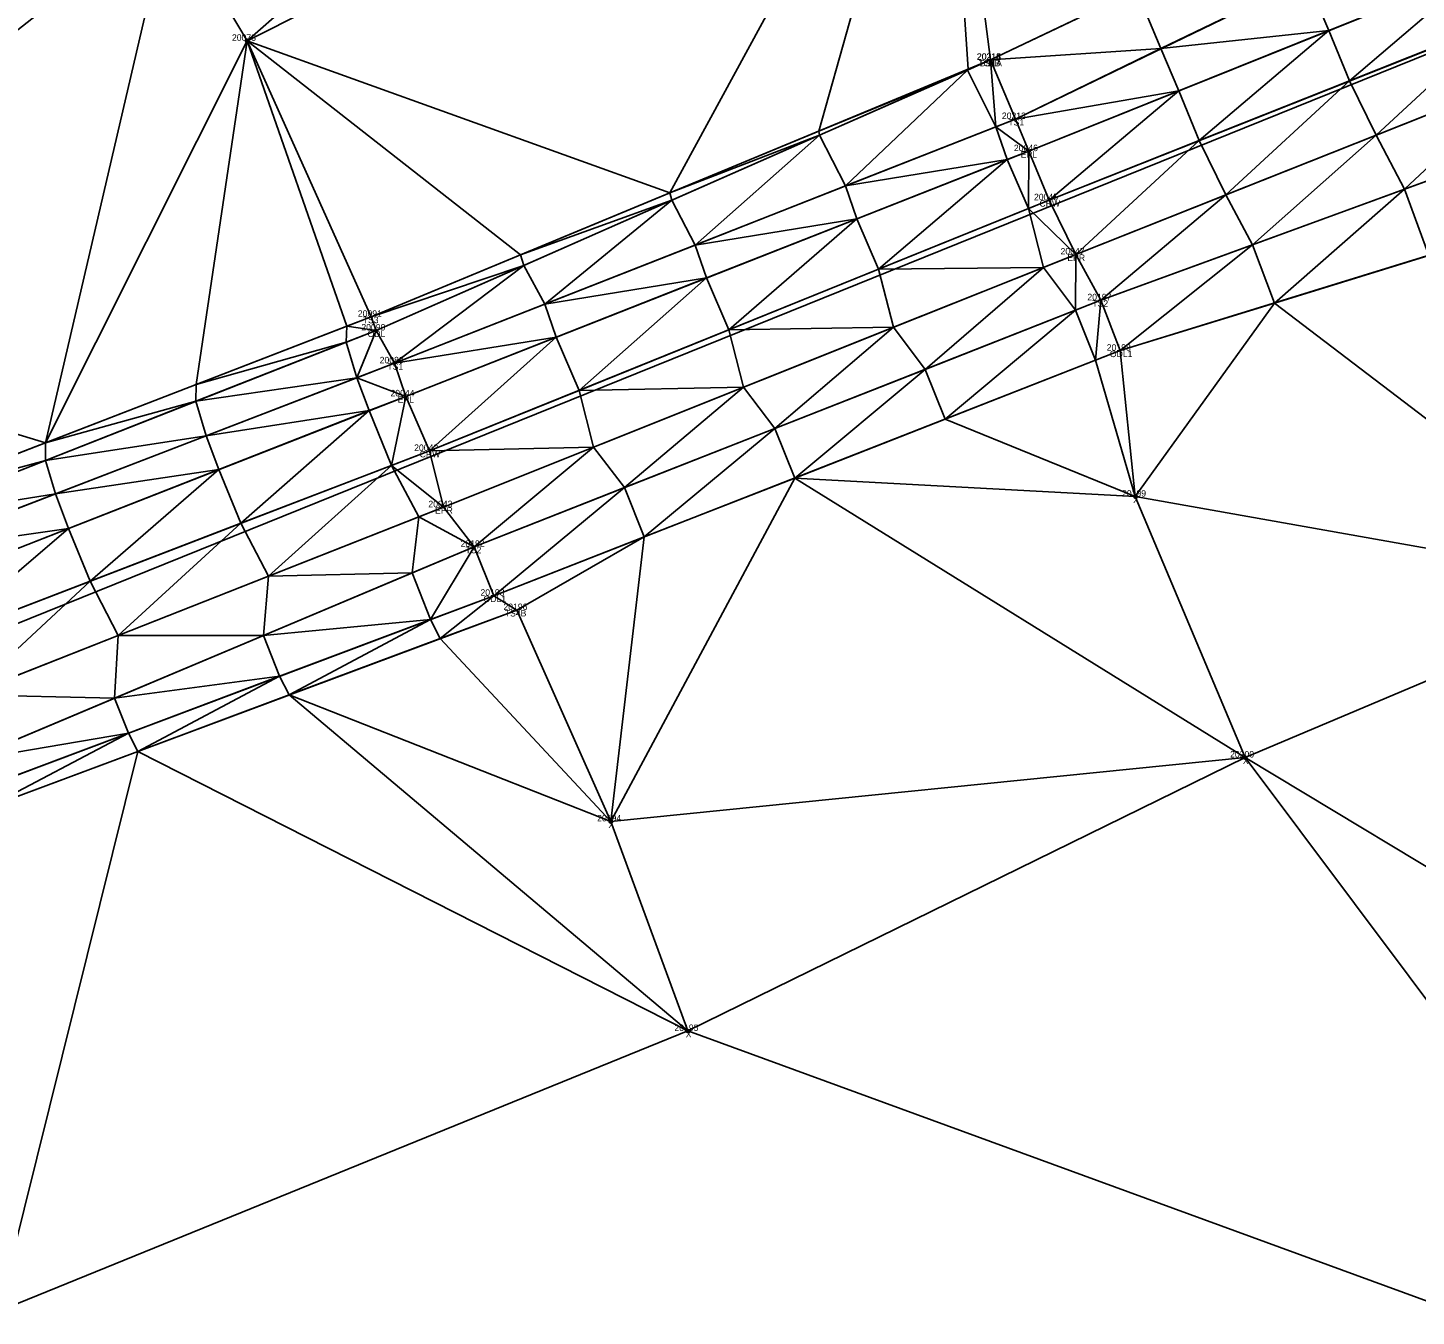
# Model space of a CAD drawing. Extents: x 1966740 to 1969291, y 1117379 to 1118460.
# Drawn here: x 1967411.8 to 1967626.6, y 1117599.2 to 1117798.6 of the extents above; entities that cross this region are included whole.
import ezdxf

# ---------------------------------------------------------------- set-up
doc = ezdxf.new("R2010")
doc.units = 0
for name, color, linetype in [('Level 1', 7, 'Continuous'), ('Level 3', 7, 'Continuous'), ('Level 30', 7, 'Continuous'), ('Level 35', 7, 'Continuous'), ('Level 50', 7, 'Continuous'), ('Level 52', 7, 'Continuous'), ('Level 53', 7, 'Continuous'), ('Level 56', 7, 'Continuous'), ('Level 6', 7, 'Continuous'), ('Level 62', 7, 'Continuous')]:
    doc.layers.add(name, color=color, linetype=linetype)

msp = doc.modelspace()

# ---------------------------------------------------------------- linework, layer by layer
at = {"layer": 'Level 1'}
msp.add_line((1966770.74, 1117448.12), (1967849.47, 1117883.86), dxfattribs=at)
at = {"layer": 'Level 3'}
for points in [[(1967560.73, 1117793.63), (1967650.63, 1117836.46), (1967680.95, 1117850.94), (1967690.95, 1117852.56), (1967700.5, 1117839.06)], [(1966768.15, 1117461.43), (1966869.41, 1117499.34), (1967070.52, 1117582.35), (1967171.25, 1117624.02), (1967269.74, 1117664.9), (1967320.21, 1117685.71), (1967369.37, 1117708.48), (1967468.51, 1117746.66), (1967564.6, 1117784.47), (1967654.68, 1117828.05), (1967680.1, 1117841.48), (1967687.91, 1117842.93), (1967691.45, 1117838.71), (1967693.03, 1117834.22)], [(1966769.51, 1117457.48), (1966870.16, 1117497.34), (1966971.19, 1117538.95), (1967071.09, 1117580.24), (1967172.6, 1117621.53), (1967270.79, 1117661.66), (1967321.12, 1117682.57), (1967371.52, 1117702.88), (1967470.26, 1117741.55), (1967566.67, 1117779.5), (1967661.25, 1117817.53), (1967694.4, 1117831.19), (1967697.89, 1117822.8)], [(1966772.57, 1117449.88), (1966874.49, 1117489.87), (1966974.64, 1117529.93), (1967075.06, 1117571.68), (1967175.91, 1117613.34), (1967274.11, 1117653.69), (1967325.25, 1117674.8), (1967374.73, 1117695.01), (1967473.9, 1117733.1), (1967569.8, 1117771.9), (1967665.19, 1117809.79), (1967697.89, 1117822.8)], [(1967340.03, 1117669.86), (1967379.26, 1117686.2), (1967476.09, 1117724.39), (1967573.92, 1117763.51), (1967667.7, 1117800.74), (1967701.64, 1117814), (1967697.89, 1117822.8)], [(1967334.06, 1117655.75), (1967334.81, 1117659.44), (1967379.1, 1117675.46), (1967480.83, 1117718.27), (1967577.81, 1117756.42), (1967702.07, 1117801.85), (1967703.17, 1117805.75), (1967702.89, 1117809.87)], [(1966766.42, 1117472.19), (1966865.47, 1117508.82), (1967066.64, 1117593.45), (1967166.55, 1117636.11), (1967264.62, 1117677.56), (1967315.66, 1117698.57), (1967367.9, 1117716.34), (1967464.92, 1117753.87), (1967560.73, 1117793.63)], [(1967334.06, 1117655.75), (1967336.84, 1117652.84), (1967381.99, 1117669.13), (1967487.42, 1117708.48)]]:
    msp.add_lwpolyline(points, dxfattribs=at)
at = {"layer": 'Level 30'}
for centre in [(1967445.69, 1117796.58), (1967583.14, 1117726.03), (1967600.11, 1117685.65), (1967501.97, 1117675.76), (1967513.9, 1117643.33)]:
    msp.add_circle(centre, 0.25, dxfattribs=at)
at = {"layer": 'Level 35'}
for points in [[(1967433.7, 1117816.8), (1967539.35, 1117878.65), (1967445.69, 1117796.58)], [(1967445.69, 1117796.58), (1967539.35, 1117878.65), (1967553.36, 1117850.76)], [(1967445.69, 1117796.58), (1967553.36, 1117850.76), (1967511.09, 1117773.03)], [(1967511.09, 1117773.03), (1967553.36, 1117850.76), (1967534.17, 1117782.61)], [(1967534.17, 1117782.61), (1967553.36, 1117850.76), (1967557.25, 1117792.19)], [(1967553.36, 1117850.76), (1967583.3, 1117804.39), (1967560.73, 1117793.63)], [(1967553.36, 1117850.76), (1967560.73, 1117793.63), (1967557.25, 1117792.19)], [(1967352.83, 1117753.13), (1967433.7, 1117816.8), (1967414.52, 1117734.37)], [(1967414.52, 1117734.37), (1967433.7, 1117816.8), (1967445.69, 1117796.58)], [(1967609.61, 1117806.25), (1967636.26, 1117807.48), (1967613.06, 1117798.15)], [(1967613.06, 1117798.15), (1967636.26, 1117807.48), (1967616.27, 1117790.36)], [(1967616.27, 1117790.36), (1967636.26, 1117807.48), (1967639.5, 1117799.59)], [(1967583.3, 1117804.39), (1967609.61, 1117806.25), (1967587.1, 1117795.36)], [(1967587.1, 1117795.36), (1967609.61, 1117806.25), (1967613.06, 1117798.15)], [(1967560.73, 1117793.63), (1967583.3, 1117804.39), (1967587.1, 1117795.36)], [(1967587.1, 1117795.36), (1967613.06, 1117798.15), (1967589.86, 1117788.83)], [(1967589.86, 1117788.83), (1967613.06, 1117798.15), (1967593.04, 1117781.13)], [(1967593.04, 1117781.13), (1967613.06, 1117798.15), (1967616.27, 1117790.36)], [(1967616.27, 1117790.36), (1967639.5, 1117799.59), (1967620.39, 1117781.96)], [(1967620.39, 1117781.96), (1967639.5, 1117799.59), (1967643.63, 1117791.18)], [(1967414.52, 1117734.37), (1967445.69, 1117796.58), (1967437.82, 1117743.38)], [(1967437.82, 1117743.38), (1967445.69, 1117796.58), (1967461.13, 1117752.4)], [(1967445.69, 1117796.58), (1967511.09, 1117773.03), (1967488, 1117763.45)], [(1967445.69, 1117796.58), (1967488, 1117763.45), (1967464.92, 1117753.87)], [(1967445.69, 1117796.58), (1967464.92, 1117753.87), (1967461.13, 1117752.4)], [(1967560.73, 1117793.63), (1967587.1, 1117795.36), (1967564.6, 1117784.47)], [(1967564.6, 1117784.47), (1967587.1, 1117795.36), (1967589.86, 1117788.83)], [(1967534.17, 1117782.61), (1967557.25, 1117792.19), (1967557.15, 1117792.05)], [(1967534.17, 1117782.61), (1967557.15, 1117792.05), (1967534.28, 1117781.98)], [(1967534.28, 1117781.98), (1967557.15, 1117792.05), (1967538.29, 1117774.12)], [(1967538.29, 1117774.12), (1967557.15, 1117792.05), (1967561.56, 1117783.28)], [(1967557.15, 1117792.05), (1967557.25, 1117792.19), (1967560.73, 1117793.63)], [(1967557.15, 1117792.05), (1967560.73, 1117793.63), (1967561.56, 1117783.28)], [(1967560.73, 1117793.63), (1967564.6, 1117784.47), (1967561.56, 1117783.28)], [(1967593.04, 1117781.13), (1967616.27, 1117790.36), (1967597.15, 1117772.73)], [(1967597.15, 1117772.73), (1967616.27, 1117790.36), (1967620.39, 1117781.96)], [(1967620.39, 1117781.96), (1967643.63, 1117791.18), (1967624.77, 1117773.59)], [(1967624.77, 1117773.59), (1967643.63, 1117791.18), (1967648.25, 1117782.17)], [(1967564.6, 1117784.47), (1967589.86, 1117788.83), (1967566.67, 1117779.5)], [(1967566.67, 1117779.5), (1967589.86, 1117788.83), (1967569.8, 1117771.9)], [(1967569.8, 1117771.9), (1967589.86, 1117788.83), (1967593.04, 1117781.13)], [(1967538.29, 1117774.12), (1967561.56, 1117783.28), (1967563.31, 1117778.18)], [(1967561.56, 1117783.28), (1967564.6, 1117784.47), (1967566.67, 1117779.5)], [(1967561.56, 1117783.28), (1967566.67, 1117779.5), (1967563.31, 1117778.18)], [(1967511.09, 1117773.03), (1967534.17, 1117782.61), (1967534.28, 1117781.98)], [(1967511.09, 1117773.03), (1967534.28, 1117781.98), (1967511.41, 1117771.9)], [(1967511.41, 1117771.9), (1967534.28, 1117781.98), (1967515.03, 1117764.97)], [(1967515.03, 1117764.97), (1967534.28, 1117781.98), (1967538.29, 1117774.12)], [(1967569.8, 1117771.9), (1967593.04, 1117781.13), (1967573.92, 1117763.51)], [(1967573.92, 1117763.51), (1967593.04, 1117781.13), (1967597.15, 1117772.73)], [(1967597.15, 1117772.73), (1967620.39, 1117781.96), (1967601.29, 1117765)], [(1967601.29, 1117765), (1967620.39, 1117781.96), (1967624.77, 1117773.59)], [(1967624.77, 1117773.59), (1967648.25, 1117782.17), (1967628.56, 1117763.37)], [(1967563.31, 1117778.18), (1967566.67, 1117779.5), (1967566.59, 1117770.6)], [(1967566.59, 1117770.6), (1967566.67, 1117779.5), (1967569.8, 1117771.9)], [(1967538.29, 1117774.12), (1967563.31, 1117778.18), (1967540.04, 1117769.02)], [(1967540.04, 1117769.02), (1967563.31, 1117778.18), (1967543.42, 1117761.22)], [(1967543.42, 1117761.22), (1967563.31, 1117778.18), (1967566.59, 1117770.6)], [(1967488, 1117763.45), (1967511.09, 1117773.03), (1967511.41, 1117771.9)], [(1967515.03, 1117764.97), (1967538.29, 1117774.12), (1967540.04, 1117769.02)], [(1967573.92, 1117763.51), (1967597.15, 1117772.73), (1967577.81, 1117756.42)], [(1967577.81, 1117756.42), (1967597.15, 1117772.73), (1967601.29, 1117765)], [(1967601.29, 1117765), (1967624.77, 1117773.59), (1967604.68, 1117755.99)], [(1967604.68, 1117755.99), (1967624.77, 1117773.59), (1967628.56, 1117763.37)], [(1967488, 1117763.45), (1967511.41, 1117771.9), (1967488.54, 1117761.82)], [(1967488.54, 1117761.82), (1967511.41, 1117771.9), (1967491.77, 1117755.81)], [(1967491.77, 1117755.81), (1967511.41, 1117771.9), (1967515.03, 1117764.97)], [(1967543.42, 1117761.22), (1967566.59, 1117770.6), (1967568.94, 1117761.51)], [(1967566.59, 1117770.6), (1967569.8, 1117771.9), (1967573.92, 1117763.51)], [(1967566.59, 1117770.6), (1967573.92, 1117763.51), (1967568.94, 1117761.51)], [(1967515.03, 1117764.97), (1967540.04, 1117769.02), (1967516.78, 1117759.87)], [(1967516.78, 1117759.87), (1967540.04, 1117769.02), (1967520.24, 1117751.85)], [(1967520.24, 1117751.85), (1967540.04, 1117769.02), (1967543.42, 1117761.22)], [(1967491.77, 1117755.81), (1967515.03, 1117764.97), (1967516.78, 1117759.87)], [(1967577.81, 1117756.42), (1967601.29, 1117765), (1967580.8, 1117748.62)], [(1967580.8, 1117748.62), (1967601.29, 1117765), (1967604.68, 1117755.99)], [(1967464.92, 1117753.87), (1967488, 1117763.45), (1967488.54, 1117761.82)], [(1967464.92, 1117753.87), (1967488.54, 1117761.82), (1967465.67, 1117751.74)], [(1967465.67, 1117751.74), (1967488.54, 1117761.82), (1967468.51, 1117746.66)], [(1967468.51, 1117746.66), (1967488.54, 1117761.82), (1967491.77, 1117755.81)], [(1967543.42, 1117761.22), (1967568.94, 1117761.51), (1967545.73, 1117752.23)], [(1967545.73, 1117752.23), (1967568.94, 1117761.51), (1967550.62, 1117745.72)], [(1967550.62, 1117745.72), (1967568.94, 1117761.51), (1967573.88, 1117754.87)], [(1967568.94, 1117761.51), (1967573.92, 1117763.51), (1967573.88, 1117754.87)], [(1967573.88, 1117754.87), (1967573.92, 1117763.51), (1967577.81, 1117756.42)], [(1967604.68, 1117755.99), (1967628.56, 1117763.37), (1967662.45, 1117711.98)], [(1967491.77, 1117755.81), (1967516.78, 1117759.87), (1967493.52, 1117750.71)], [(1967493.52, 1117750.71), (1967516.78, 1117759.87), (1967497.07, 1117742.47)], [(1967497.07, 1117742.47), (1967516.78, 1117759.87), (1967520.24, 1117751.85)], [(1967520.24, 1117751.85), (1967543.42, 1117761.22), (1967545.73, 1117752.23)], [(1967468.51, 1117746.66), (1967491.77, 1117755.81), (1967493.52, 1117750.71)], [(1967573.88, 1117754.87), (1967577.81, 1117756.42), (1967576.99, 1117747.13)], [(1967576.99, 1117747.13), (1967577.81, 1117756.42), (1967580.8, 1117748.62)], [(1967580.8, 1117748.62), (1967604.68, 1117755.99), (1967583.14, 1117726.03)], [(1967583.14, 1117726.03), (1967604.68, 1117755.99), (1967662.45, 1117711.98)], [(1967352.83, 1117753.13), (1967414.52, 1117734.37), (1967391.21, 1117725.35)], [(1967461.13, 1117752.4), (1967464.92, 1117753.87), (1967465.67, 1117751.74)], [(1967550.62, 1117745.72), (1967573.88, 1117754.87), (1967553.72, 1117738.02)], [(1967553.72, 1117738.02), (1967573.88, 1117754.87), (1967576.99, 1117747.13)], [(1967437.82, 1117743.38), (1967461.13, 1117752.4), (1967461.04, 1117749.92)], [(1967461.04, 1117749.92), (1967461.13, 1117752.4), (1967465.67, 1117751.74)], [(1967461.04, 1117749.92), (1967465.67, 1117751.74), (1967462.68, 1117744.41)], [(1967462.68, 1117744.41), (1967465.67, 1117751.74), (1967468.51, 1117746.66)], [(1967497.07, 1117742.47), (1967520.24, 1117751.85), (1967522.52, 1117742.95)], [(1967520.24, 1117751.85), (1967545.73, 1117752.23), (1967522.52, 1117742.95)], [(1967522.52, 1117742.95), (1967545.73, 1117752.23), (1967527.35, 1117736.57)], [(1967527.35, 1117736.57), (1967545.73, 1117752.23), (1967550.62, 1117745.72)], [(1967437.78, 1117740.78), (1967461.04, 1117749.92), (1967462.68, 1117744.41)], [(1967437.78, 1117740.78), (1967437.82, 1117743.38), (1967461.04, 1117749.92)], [(1967468.51, 1117746.66), (1967493.52, 1117750.71), (1967470.26, 1117741.55)], [(1967470.26, 1117741.55), (1967493.52, 1117750.71), (1967473.9, 1117733.1)], [(1967473.9, 1117733.1), (1967493.52, 1117750.71), (1967497.07, 1117742.47)], [(1967576.99, 1117747.13), (1967580.8, 1117748.62), (1967583.14, 1117726.03)], [(1967462.68, 1117744.41), (1967468.51, 1117746.66), (1967470.26, 1117741.55)], [(1967553.72, 1117738.02), (1967576.99, 1117747.13), (1967583.14, 1117726.03)], [(1967437.78, 1117740.78), (1967462.68, 1117744.41), (1967439.35, 1117735.43)], [(1967439.35, 1117735.43), (1967462.68, 1117744.41), (1967464.61, 1117739.34)], [(1967462.68, 1117744.41), (1967470.26, 1117741.55), (1967464.61, 1117739.34)], [(1967527.35, 1117736.57), (1967550.62, 1117745.72), (1967530.44, 1117728.91)], [(1967530.44, 1117728.91), (1967550.62, 1117745.72), (1967553.72, 1117738.02)], [(1967414.52, 1117734.37), (1967437.82, 1117743.38), (1967437.78, 1117740.78)], [(1967473.9, 1117733.1), (1967497.07, 1117742.47), (1967499.3, 1117733.67)], [(1967497.07, 1117742.47), (1967522.52, 1117742.95), (1967499.3, 1117733.67)], [(1967499.3, 1117733.67), (1967522.52, 1117742.95), (1967504.09, 1117727.42)], [(1967504.09, 1117727.42), (1967522.52, 1117742.95), (1967527.35, 1117736.57)], [(1967414.52, 1117734.37), (1967437.78, 1117740.78), (1967414.52, 1117731.63)], [(1967414.52, 1117731.63), (1967437.78, 1117740.78), (1967439.35, 1117735.43)], [(1967464.61, 1117739.34), (1967470.26, 1117741.55), (1967468.07, 1117730.86)], [(1967468.07, 1117730.86), (1967470.26, 1117741.55), (1967473.9, 1117733.1)], [(1967439.35, 1117735.43), (1967464.61, 1117739.34), (1967441.34, 1117730.23)], [(1967441.34, 1117730.23), (1967464.61, 1117739.34), (1967444.73, 1117721.9)], [(1967444.73, 1117721.9), (1967464.61, 1117739.34), (1967468.07, 1117730.86)], [(1967530.44, 1117728.91), (1967553.72, 1117738.02), (1967583.14, 1117726.03)], [(1967504.09, 1117727.42), (1967527.35, 1117736.57), (1967507.16, 1117719.81)], [(1967507.16, 1117719.81), (1967527.35, 1117736.57), (1967530.44, 1117728.91)], [(1967391.21, 1117725.35), (1967414.52, 1117734.37), (1967414.52, 1117731.63)], [(1967414.52, 1117731.63), (1967439.35, 1117735.43), (1967416.03, 1117726.45)], [(1967416.03, 1117726.45), (1967439.35, 1117735.43), (1967441.34, 1117730.23)], [(1967473.9, 1117733.1), (1967499.3, 1117733.67), (1967476.09, 1117724.39)], [(1967476.09, 1117724.39), (1967499.3, 1117733.67), (1967480.83, 1117718.27)], [(1967480.83, 1117718.27), (1967499.3, 1117733.67), (1967504.09, 1117727.42)], [(1967391.21, 1117725.35), (1967414.52, 1117731.63), (1967391.27, 1117722.49)], [(1967391.27, 1117722.49), (1967414.52, 1117731.63), (1967416.03, 1117726.45)], [(1967468.07, 1117730.86), (1967473.9, 1117733.1), (1967476.09, 1117724.39)], [(1967416.03, 1117726.45), (1967441.34, 1117730.23), (1967418.07, 1117721.11)], [(1967418.07, 1117721.11), (1967441.34, 1117730.23), (1967421.4, 1117712.93)], [(1967421.4, 1117712.93), (1967441.34, 1117730.23), (1967444.73, 1117721.9)], [(1967444.73, 1117721.9), (1967468.07, 1117730.86), (1967449.02, 1117713.71)], [(1967449.02, 1117713.71), (1967468.07, 1117730.86), (1967472.27, 1117722.88)], [(1967468.07, 1117730.86), (1967476.09, 1117724.39), (1967472.27, 1117722.88)], [(1967480.83, 1117718.27), (1967504.09, 1117727.42), (1967483.89, 1117710.7)], [(1967483.89, 1117710.7), (1967504.09, 1117727.42), (1967507.16, 1117719.81)], [(1967501.97, 1117675.76), (1967507.16, 1117719.81), (1967530.44, 1117728.91)], [(1967501.97, 1117675.76), (1967530.44, 1117728.91), (1967600.11, 1117685.65)], [(1967530.44, 1117728.91), (1967583.14, 1117726.03), (1967600.11, 1117685.65)], [(1967391.27, 1117722.49), (1967416.03, 1117726.45), (1967392.7, 1117717.46)], [(1967392.7, 1117717.46), (1967416.03, 1117726.45), (1967418.07, 1117721.11)], [(1967583.14, 1117726.03), (1967662.45, 1117711.98), (1967600.11, 1117685.65)], [(1967449.02, 1117713.71), (1967472.27, 1117722.88), (1967471.26, 1117714.24)], [(1967471.26, 1117714.24), (1967472.27, 1117722.88), (1967480.83, 1117718.27)], [(1967472.27, 1117722.88), (1967476.09, 1117724.39), (1967480.83, 1117718.27)], [(1967392.7, 1117717.46), (1967418.07, 1117721.11), (1967394.79, 1117711.99)], [(1967394.79, 1117711.99), (1967418.07, 1117721.11), (1967398.07, 1117703.97)], [(1967398.07, 1117703.97), (1967418.07, 1117721.11), (1967421.4, 1117712.93)], [(1967421.4, 1117712.93), (1967444.73, 1117721.9), (1967425.76, 1117704.54)], [(1967425.76, 1117704.54), (1967444.73, 1117721.9), (1967449.02, 1117713.71)], [(1967483.89, 1117710.7), (1967507.16, 1117719.81), (1967487.42, 1117708.48)], [(1967487.42, 1117708.48), (1967507.16, 1117719.81), (1967501.97, 1117675.76)], [(1967471.26, 1117714.24), (1967480.83, 1117718.27), (1967474.1, 1117707.02)], [(1967474.1, 1117707.02), (1967480.83, 1117718.27), (1967483.89, 1117710.7)], [(1967448.22, 1117704.55), (1967449.02, 1117713.71), (1967471.26, 1117714.24)], [(1967448.22, 1117704.55), (1967471.26, 1117714.24), (1967474.1, 1117707.02)], [(1967398.07, 1117703.97), (1967421.4, 1117712.93), (1967402.51, 1117695.37)], [(1967402.51, 1117695.37), (1967421.4, 1117712.93), (1967425.76, 1117704.54)], [(1967425.76, 1117704.54), (1967449.02, 1117713.71), (1967448.22, 1117704.55)], [(1967474.1, 1117707.02), (1967483.89, 1117710.7), (1967475.6, 1117704.07)], [(1967475.6, 1117704.07), (1967483.89, 1117710.7), (1967487.42, 1117708.48)], [(1967600.11, 1117685.65), (1967662.45, 1117711.98), (1967681.31, 1117636.77)], [(1967475.6, 1117704.07), (1967487.42, 1117708.48), (1967501.97, 1117675.76)], [(1967448.22, 1117704.55), (1967474.1, 1117707.02), (1967450.72, 1117698.23)], [(1967450.72, 1117698.23), (1967474.1, 1117707.02), (1967452.2, 1117695.34)], [(1967452.2, 1117695.34), (1967474.1, 1117707.02), (1967475.6, 1117704.07)], [(1967402.51, 1117695.37), (1967425.76, 1117704.54), (1967425.18, 1117694.85)], [(1967425.18, 1117694.85), (1967425.76, 1117704.54), (1967448.22, 1117704.55)], [(1967425.18, 1117694.85), (1967448.22, 1117704.55), (1967450.72, 1117698.23)], [(1967452.2, 1117695.34), (1967475.6, 1117704.07), (1967501.97, 1117675.76)], [(1967425.18, 1117694.85), (1967450.72, 1117698.23), (1967427.33, 1117689.43)], [(1967427.33, 1117689.43), (1967450.72, 1117698.23), (1967428.8, 1117686.6)], [(1967428.8, 1117686.6), (1967450.72, 1117698.23), (1967452.2, 1117695.34)], [(1967402.14, 1117685.16), (1967402.51, 1117695.37), (1967425.18, 1117694.85)], [(1967428.8, 1117686.6), (1967452.2, 1117695.34), (1967513.9, 1117643.33)], [(1967452.2, 1117695.34), (1967501.97, 1117675.76), (1967513.9, 1117643.33)], [(1967402.14, 1117685.16), (1967425.18, 1117694.85), (1967427.33, 1117689.43)], [(1967402.14, 1117685.16), (1967427.33, 1117689.43), (1967403.94, 1117680.64)], [(1967403.94, 1117680.64), (1967427.33, 1117689.43), (1967405.39, 1117677.87)], [(1967405.39, 1117677.87), (1967427.33, 1117689.43), (1967428.8, 1117686.6)], [(1967405.39, 1117677.87), (1967428.8, 1117686.6), (1967407.22, 1117599.96)], [(1967407.22, 1117599.96), (1967428.8, 1117686.6), (1967513.9, 1117643.33)], [(1967501.97, 1117675.76), (1967600.11, 1117685.65), (1967513.9, 1117643.33)], [(1967513.9, 1117643.33), (1967600.11, 1117685.65), (1967676.25, 1117583.97)], [(1967600.11, 1117685.65), (1967681.31, 1117636.77), (1967676.25, 1117583.97)]]:
    msp.add_lwpolyline(points, close=True, dxfattribs=at)
at = {"layer": 'Level 50'}
for centre in [(1967560.73, 1117793.63), (1967560.73, 1117793.63), (1967560.73, 1117793.63), (1967564.6, 1117784.47), (1967566.67, 1117779.5), (1967569.8, 1117771.9), (1967573.92, 1117763.51), (1967577.81, 1117756.42), (1967464.92, 1117753.87), (1967465.67, 1117751.74), (1967580.8, 1117748.62), (1967468.51, 1117746.66), (1967470.26, 1117741.55), (1967473.9, 1117733.1), (1967476.09, 1117724.39), (1967480.83, 1117718.27), (1967483.89, 1117710.7), (1967487.42, 1117708.48)]:
    msp.add_circle(centre, 0.001, dxfattribs=at)
at = {"layer": 'Level 6'}
for points in [[(1966766.64, 1117466.58), (1966867.24, 1117504.5), (1967068.76, 1117586.41), (1967167.95, 1117632.67), (1967266.82, 1117671.88), (1967316.79, 1117693.47), (1967368.01, 1117713.34), (1967465.67, 1117751.74), (1967560.73, 1117793.63)], [(1967336.04, 1117656.91), (1967380.56, 1117671.84), (1967483.89, 1117710.7), (1967580.8, 1117748.62), (1967673.4, 1117777.22)]]:
    msp.add_lwpolyline(points, dxfattribs=at)

# ---------------------------------------------------------------- texts
at = {"layer": 'Level 52'}
for s, p in [('20073', (1967443.36, 1117796.58)), ('20199', (1967581.08, 1117726.03)), ('20200', (1967597.8, 1117685.65)), ('20194', (1967499.86, 1117675.76)), ('20195', (1967511.82, 1117643.33))]:
    msp.add_text(s, height=1, dxfattribs=at).set_placement(p)
at = {"layer": 'Level 53'}
for s, p in [('20215', (1967558.63, 1117793.63)), ('20216', (1967558.65, 1117793.63)), ('TS3B', (1967558.91, 1117792.63)), ('BS1A', (1967559.07, 1117792.63)), ('20213', (1967562.49, 1117784.47)), ('TS1', (1967563.49, 1117783.47)), ('20046', (1967564.35, 1117779.5)), ('EPL', (1967565.41, 1117778.5)), ('20045', (1967567.46, 1117771.9)), ('CRW', (1967568.31, 1117770.9)), ('20047', (1967571.57, 1117763.51)), ('EPR', (1967572.62, 1117762.51)), ('20197', (1967575.72, 1117756.42)), ('TS2', (1967576.48, 1117755.42)), ('20091', (1967462.84, 1117753.87)), ('TS3', (1967463.59, 1117752.87)), ('20198', (1967578.72, 1117748.62)), ('ODL1', (1967579.2, 1117747.62)), ('20089', (1967466.21, 1117746.66)), ('TS1', (1967467.4, 1117745.66)), ('20044', (1967467.89, 1117741.55)), ('EPL', (1967469, 1117740.55)), ('20042', (1967471.55, 1117733.1)), ('CRW', (1967472.4, 1117732.1)), ('20043', (1967473.75, 1117724.39)), ('EPR', (1967474.79, 1117723.39)), ('20192', (1967478.74, 1117718.27)), ('TS2', (1967479.5, 1117717.27)), ('20193', (1967481.81, 1117710.7)), ('ODL1', (1967482.28, 1117709.7)), ('20196', (1967485.36, 1117708.48)), ('TS4B', (1967485.57, 1117707.48))]:
    msp.add_text(s, height=1, dxfattribs=at).set_placement(p)
at = {"layer": 'Level 56'}
for s, p in [('20214', (1967558.6, 1117793.63)), ('B', (1967560.4, 1117792.63)), ('20090', (1967463.38, 1117751.74)), ('ODL', (1967464.34, 1117750.74))]:
    msp.add_text(s, height=1, dxfattribs=at).set_placement(p)
at = {"layer": 'Level 62'}
for p in [(1967445.35, 1117795.58), (1967582.8, 1117725.03), (1967599.78, 1117684.65), (1967501.63, 1117674.76), (1967513.57, 1117642.33)]:
    msp.add_text('X', height=1, dxfattribs=at).set_placement(p)

doc.saveas('drawing.dxf')
